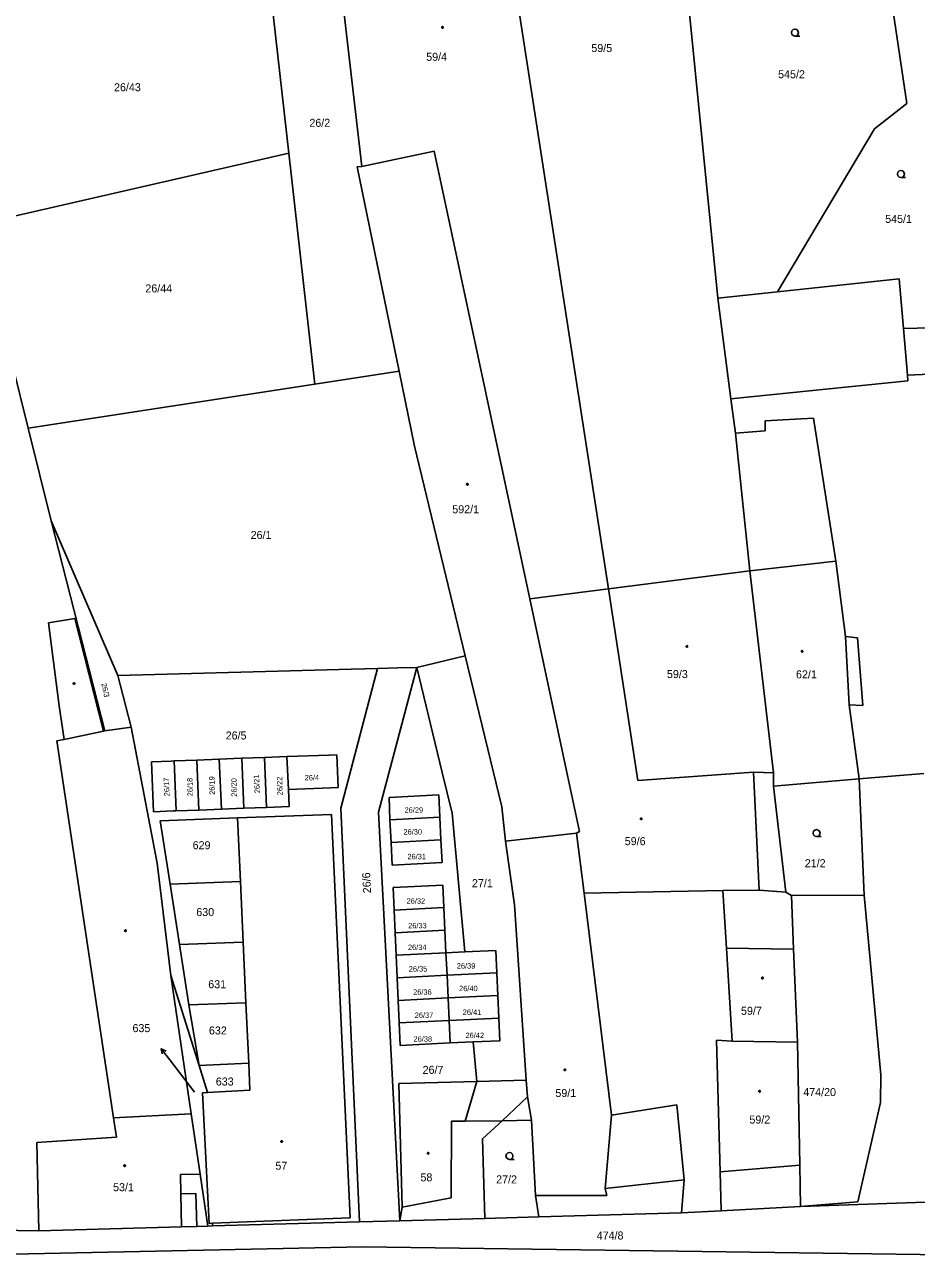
# Model space of a CAD drawing. Extents: x -757994 to -755874, y -1047691 to -1046119.
# Drawn here: x -757304.1 to -757209.4, y -1046980.7 to -1046849.4 of the extents above; entities that cross this region are included whole.
import ezdxf

# ---------------------------------------------------------------- set-up
doc = ezdxf.new("R2010")
doc.units = 0
doc.layers.add('katastrální mapa', color=7, linetype='Continuous')

msp = doc.modelspace()

# ---------------------------------------------------------------- linework, layer by layer
at = {"layer": 'katastrální mapa'}
for p, q in [((-757254.51, -1046829.16), (-757242.14, -1046909.26)), ((-757271.62, -1046835.82), (-757268.32, -1046864.4)), ((-757278.84, -1046838.68), (-757276.08, -1046863.01)), ((-757230.53, -1046878.4), (-757233.81, -1046845.4)), ((-757276.08, -1046863.01), (-757309.14, -1046870.58)), ((-757276.08, -1046863.01), (-757273.31, -1046887.52)), ((-757260.65, -1046862.78), (-757268.32, -1046864.4)), ((-757260.65, -1046862.78), (-757250.48, -1046910.32)), ((-757268.32, -1046864.4), (-757268.81, -1046864.45)), ((-757268.81, -1046864.45), (-757264.36, -1046886.13)), ((-757303.78, -1046892.18), (-757309.14, -1046870.58)), ((-757211.24, -1046876.35), (-757224.17, -1046877.72)), ((-757210.79, -1046881.6), (-757211.24, -1046876.35)), ((-757224.17, -1046877.72), (-757230.53, -1046878.4)), ((-757229.13, -1046889.09), (-757230.53, -1046878.4)), ((-757206.44, -1046881.51), (-757210.79, -1046881.6)), ((-757210.37, -1046886.58), (-757210.79, -1046881.6)), ((-757264.36, -1046886.13), (-757273.31, -1046887.52)), ((-757264.36, -1046886.13), (-757262.73, -1046894.1)), ((-757200.85, -1046886.14), (-757210.37, -1046886.58)), ((-757210.32, -1046887.18), (-757210.37, -1046886.58)), ((-757273.31, -1046887.52), (-757303.78, -1046892.18)), ((-757229.13, -1046889.09), (-757210.32, -1046887.18)), ((-757228.65, -1046892.73), (-757229.13, -1046889.09)), ((-757225.5, -1046891.42), (-757220.35, -1046891.15)), ((-757225.48, -1046892.47), (-757225.5, -1046891.42)), ((-757220.35, -1046891.15), (-757217.99, -1046906.33)), ((-757301.34, -1046902.02), (-757303.78, -1046892.18)), ((-757228.65, -1046892.73), (-757225.48, -1046892.47)), ((-757227.1, -1046907.35), (-757228.65, -1046892.73)), ((-757262.73, -1046894.1), (-757257.34, -1046916.35)), ((-757301.34, -1046902.02), (-757295.61, -1046924.32)), ((-757301.34, -1046902.02), (-757294.23, -1046918.44)), ((-757217.99, -1046906.33), (-757227.1, -1046907.35)), ((-757217.99, -1046906.33), (-757216.95, -1046914.33)), ((-757242.14, -1046909.26), (-757227.1, -1046907.35)), ((-757224.61, -1046928.8), (-757227.1, -1046907.35)), ((-757250.48, -1046910.32), (-757242.14, -1046909.26)), ((-757250.48, -1046910.32), (-757246.48, -1046929.06)), ((-757242.14, -1046909.26), (-757239, -1046929.62)), ((-757301.6, -1046912.85), (-757298.8, -1046912.42)), ((-757300.49, -1046921.68), (-757301.6, -1046912.85)), ((-757298.8, -1046912.42), (-757295.78, -1046924.36)), ((-757216.95, -1046914.33), (-757215.68, -1046914.44)), ((-757216.95, -1046914.33), (-757216.55, -1046921.56)), ((-757215.68, -1046914.44), (-757215.12, -1046921.64)), ((-757257.34, -1046916.35), (-757262.49, -1046917.6)), ((-757257.34, -1046916.35), (-757253.45, -1046932.4)), ((-757294.23, -1046918.44), (-757269.43, -1046917.78)), ((-757270.57, -1046932.54), (-757266.66, -1046917.71)), ((-757266.66, -1046917.71), (-757269.43, -1046917.78)), ((-757264.51, -1046917.65), (-757266.66, -1046917.71)), ((-757264.51, -1046917.65), (-757262.49, -1046917.6)), ((-757264.22, -1046924.15), (-757262.49, -1046917.6)), ((-757262.49, -1046917.6), (-757259.78, -1046928.74)), ((-757294.23, -1046918.44), (-757292.82, -1046923.93)), ((-757299.93, -1046925.24), (-757300.49, -1046921.68)), ((-757215.12, -1046921.64), (-757216.55, -1046921.56)), ((-757216.55, -1046921.56), (-757215.51, -1046929.42)), ((-757299.93, -1046925.24), (-757295.78, -1046924.36)), ((-757295.78, -1046924.36), (-757295.61, -1046924.32)), ((-757295.61, -1046924.32), (-757292.82, -1046923.93)), ((-757292.82, -1046923.93), (-757290.05, -1046938.37)), ((-757264.22, -1046924.15), (-757266.55, -1046932.97)), ((-757300.71, -1046925.41), (-757299.93, -1046925.24)), ((-757294.71, -1046965.41), (-757300.71, -1046925.41)), ((-757288.25, -1046927.53), (-757285.86, -1046927.44)), ((-757285.86, -1046927.44), (-757283.47, -1046927.35)), ((-757285.65, -1046932.74), (-757285.86, -1046927.44)), ((-757283.47, -1046927.35), (-757281.07, -1046927.25)), ((-757283.25, -1046932.64), (-757283.47, -1046927.35)), ((-757281.07, -1046927.25), (-757278.68, -1046927.16)), ((-757280.85, -1046932.55), (-757281.07, -1046927.25)), ((-757278.68, -1046927.16), (-757276.28, -1046927.07)), ((-757278.45, -1046932.46), (-757278.68, -1046927.16)), ((-757276.28, -1046927.07), (-757271.78, -1046926.9)), ((-757276.13, -1046930.57), (-757276.28, -1046927.07)), ((-757271.78, -1046926.9), (-757270.99, -1046926.87)), ((-757270.99, -1046926.87), (-757270.85, -1046930.36)), ((-757290.66, -1046927.62), (-757288.57, -1046927.54)), ((-757290.46, -1046932.92), (-757290.66, -1046927.62)), ((-757288.57, -1046927.54), (-757288.25, -1046927.53)), ((-757288.06, -1046932.83), (-757288.25, -1046927.53)), ((-757258.73, -1046933.06), (-757259.78, -1046928.74)), ((-757239, -1046929.62), (-757226.73, -1046928.72)), ((-757226.73, -1046928.72), (-757224.61, -1046928.8)), ((-757226.14, -1046941.25), (-757226.73, -1046928.72)), ((-757246.48, -1046929.06), (-757245.2, -1046935.03)), ((-757224.6, -1046930.2), (-757224.61, -1046928.8)), ((-757215.51, -1046929.42), (-757224.6, -1046930.2)), ((-757208.63, -1046928.85), (-757215.51, -1046929.42)), ((-757215.51, -1046929.42), (-757214.96, -1046941.79)), ((-757276.13, -1046930.57), (-757271.65, -1046930.39)), ((-757276.05, -1046932.37), (-757276.13, -1046930.57)), ((-757271.65, -1046930.39), (-757270.85, -1046930.36)), ((-757260.16, -1046931.13), (-757265.44, -1046931.4)), ((-757265.34, -1046933.79), (-757265.44, -1046931.4)), ((-757260.16, -1046931.13), (-757260.05, -1046933.51)), ((-757223.3, -1046941.45), (-757224.6, -1046930.2)), ((-757285.65, -1046932.74), (-757283.25, -1046932.64)), ((-757283.25, -1046932.64), (-757280.85, -1046932.55)), ((-757280.85, -1046932.55), (-757278.45, -1046932.46)), ((-757278.45, -1046932.46), (-757276.05, -1046932.37)), ((-757268.59, -1046976.47), (-757270.57, -1046932.54)), ((-757253.45, -1046932.4), (-757253.05, -1046936.05)), ((-757288.37, -1046932.84), (-757290.46, -1046932.92)), ((-757281.54, -1046933.58), (-757289.75, -1046933.89)), ((-757288.7, -1046940.6), (-757289.75, -1046933.89)), ((-757288.37, -1046932.84), (-757288.06, -1046932.83)), ((-757288.06, -1046932.83), (-757285.65, -1046932.74)), ((-757271.54, -1046933.2), (-757281.54, -1046933.58)), ((-757281.23, -1046940.32), (-757281.54, -1046933.58)), ((-757271.54, -1046933.2), (-757269.58, -1046976.04)), ((-757266.55, -1046932.97), (-757264.3, -1046976.35)), ((-757260.05, -1046933.51), (-757265.34, -1046933.79)), ((-757265.21, -1046936.18), (-757265.34, -1046933.79)), ((-757260.05, -1046933.51), (-757259.93, -1046935.91)), ((-757257.37, -1046947.8), (-757258.73, -1046933.06)), ((-757253.05, -1046936.05), (-757245.51, -1046935.21)), ((-757245.51, -1046935.21), (-757245.2, -1046935.03)), ((-757245.51, -1046935.21), (-757244.72, -1046941.56)), ((-757259.93, -1046935.91), (-757265.21, -1046936.18)), ((-757265.21, -1046936.18), (-757265.09, -1046938.58)), ((-757259.93, -1046935.91), (-757259.8, -1046938.3)), ((-757253.05, -1046936.05), (-757252.1, -1046942.8)), ((-757290.05, -1046938.37), (-757288.6, -1046950.31)), ((-757259.8, -1046938.3), (-757265.09, -1046938.58)), ((-757288.7, -1046940.6), (-757281.23, -1046940.32)), ((-757281.23, -1046940.32), (-757280.93, -1046946.76)), ((-757287.7, -1046947.02), (-757288.7, -1046940.6)), ((-757265, -1046940.97), (-757259.72, -1046940.7)), ((-757265, -1046940.97), (-757264.9, -1046943.37)), ((-757259.61, -1046943.1), (-757259.72, -1046940.7)), ((-757244.72, -1046941.56), (-757229.98, -1046941.28)), ((-757244.72, -1046941.56), (-757241.8, -1046965.13)), ((-757229.98, -1046941.28), (-757226.14, -1046941.25)), ((-757229.61, -1046947.39), (-757229.98, -1046941.28)), ((-757226.14, -1046941.25), (-757223.3, -1046941.45)), ((-757222.69, -1046941.8), (-757223.3, -1046941.45)), ((-757214.96, -1046941.79), (-757222.69, -1046941.8)), ((-757222.46, -1046947.53), (-757222.69, -1046941.8)), ((-757214.96, -1046941.79), (-757213.2, -1046960.86)), ((-757264.9, -1046943.37), (-757259.61, -1046943.1)), ((-757259.5, -1046945.49), (-757259.61, -1046943.1)), ((-757252.1, -1046942.8), (-757250.89, -1046961.43)), ((-757264.9, -1046943.37), (-757264.79, -1046945.77)), ((-757264.79, -1046945.77), (-757259.5, -1046945.49)), ((-757264.79, -1046945.77), (-757264.68, -1046948.16)), ((-757259.39, -1046947.89), (-757259.5, -1046945.49)), ((-757287.7, -1046947.02), (-757280.93, -1046946.76)), ((-757286.7, -1046953.44), (-757287.7, -1046947.02)), ((-757280.93, -1046946.76), (-757280.64, -1046953.2)), ((-757264.68, -1046948.16), (-757259.39, -1046947.89)), ((-757264.68, -1046948.16), (-757264.57, -1046950.56)), ((-757259.39, -1046947.89), (-757257.37, -1046947.8)), ((-757259.28, -1046950.28), (-757259.39, -1046947.89)), ((-757257.37, -1046947.8), (-757254.1, -1046947.65)), ((-757254.1, -1046947.65), (-757253.99, -1046950.04)), ((-757229, -1046957.27), (-757229.61, -1046947.39)), ((-757229.61, -1046947.39), (-757222.46, -1046947.53)), ((-757222.06, -1046957.37), (-757222.46, -1046947.53)), ((-757286.44, -1046964.99), (-757288.6, -1046950.31)), ((-757288.6, -1046950.31), (-757285.62, -1046959.85)), ((-757264.57, -1046950.56), (-757259.28, -1046950.28)), ((-757264.57, -1046950.56), (-757264.46, -1046952.95)), ((-757253.99, -1046950.04), (-757259.28, -1046950.28)), ((-757259.17, -1046952.68), (-757259.28, -1046950.28)), ((-757253.88, -1046952.44), (-757253.99, -1046950.04)), ((-757286.7, -1046953.44), (-757280.64, -1046953.2)), ((-757285.62, -1046959.85), (-757286.7, -1046953.44)), ((-757280.64, -1046953.2), (-757280.34, -1046959.63)), ((-757264.46, -1046952.95), (-757259.17, -1046952.68)), ((-757264.46, -1046952.95), (-757264.35, -1046955.35)), ((-757253.88, -1046952.44), (-757259.17, -1046952.68)), ((-757259.06, -1046955.08), (-757259.17, -1046952.68)), ((-757253.77, -1046954.84), (-757253.88, -1046952.44)), ((-757253.77, -1046954.84), (-757259.06, -1046955.08)), ((-757253.77, -1046954.84), (-757253.66, -1046957.23)), ((-757264.35, -1046955.35), (-757259.06, -1046955.08)), ((-757264.35, -1046955.35), (-757264.24, -1046957.75)), ((-757259.06, -1046955.08), (-757258.96, -1046957.47)), ((-757264.24, -1046957.75), (-757258.96, -1046957.47)), ((-757258.96, -1046957.47), (-757256.49, -1046957.36)), ((-757256.49, -1046957.36), (-757253.66, -1046957.23)), ((-757256.1, -1046961.56), (-757256.49, -1046957.36)), ((-757230.28, -1046971.14), (-757230.67, -1046957.18)), ((-757230.67, -1046957.18), (-757229, -1046957.27)), ((-757229, -1046957.27), (-757222.06, -1046957.37)), ((-757221.82, -1046970.44), (-757222.06, -1046957.37)), ((-757289.63, -1046958.09), (-757288.71, -1046959.28)), ((-757286.09, -1046962.68), (-757288.71, -1046959.28)), ((-757285.62, -1046959.85), (-757280.34, -1046959.63)), ((-757285.62, -1046959.85), (-757284.72, -1046962.73)), ((-757280.34, -1046959.63), (-757280.21, -1046962.49)), ((-757256.1, -1046961.56), (-757264.4, -1046961.78)), ((-757256.1, -1046961.56), (-757257.34, -1046965.79)), ((-757250.89, -1046961.43), (-757256.1, -1046961.56)), ((-757250.89, -1046961.43), (-757250.72, -1046963.2)), ((-757213.2, -1046960.86), (-757213.24, -1046963.78)), ((-757284.72, -1046962.73), (-757285.24, -1046962.76)), ((-757284.56, -1046976.63), (-757285.24, -1046962.76)), ((-757284.72, -1046962.73), (-757280.21, -1046962.49)), ((-757264.4, -1046961.78), (-757264.05, -1046974.89)), ((-757253.43, -1046965.73), (-757250.72, -1046963.2)), ((-757250.72, -1046963.2), (-757250.3, -1046965.68)), ((-757234.86, -1046964.04), (-757241.8, -1046965.13)), ((-757234.1, -1046972.01), (-757234.86, -1046964.04)), ((-757213.24, -1046963.78), (-757215.64, -1046974.34)), ((-757294.71, -1046965.41), (-757286.44, -1046964.99)), ((-757294.71, -1046965.41), (-757294.4, -1046967.49)), ((-757286.44, -1046964.99), (-757285.5, -1046971.39)), ((-757241.8, -1046965.13), (-757242.48, -1046972.91)), ((-757258.82, -1046965.79), (-757258.83, -1046973.92)), ((-757258.82, -1046965.79), (-757257.34, -1046965.79)), ((-757257.34, -1046965.79), (-757253.43, -1046965.73)), ((-757255.5, -1046967.66), (-757253.43, -1046965.73)), ((-757253.43, -1046965.73), (-757250.3, -1046965.68)), ((-757250.3, -1046965.68), (-757249.89, -1046973.65)), ((-757294.4, -1046967.49), (-757302.84, -1046968.03)), ((-757302.84, -1046968.03), (-757302.64, -1046977.41)), ((-757255.27, -1046976.1), (-757255.5, -1046967.66)), ((-757221.82, -1046970.44), (-757230.28, -1046971.14)), ((-757221.74, -1046974.83), (-757221.82, -1046970.44)), ((-757287.59, -1046971.44), (-757285.5, -1046971.39)), ((-757287.54, -1046973.49), (-757287.59, -1046971.44)), ((-757285.5, -1046971.39), (-757284.69, -1046976.91)), ((-757242.48, -1046972.91), (-757234.1, -1046972.01)), ((-757234.1, -1046972.01), (-757234.38, -1046975.52)), ((-757230.16, -1046975.29), (-757230.28, -1046971.14)), ((-757242.48, -1046972.91), (-757242.32, -1046973.68)), ((-757285.96, -1046973.45), (-757287.54, -1046973.49)), ((-757287.47, -1046976.99), (-757287.54, -1046973.49)), ((-757285.87, -1046976.95), (-757285.96, -1046973.45)), ((-757258.83, -1046973.92), (-757264.05, -1046974.89)), ((-757249.89, -1046973.65), (-757249.51, -1046975.94)), ((-757242.32, -1046973.68), (-757249.89, -1046973.65)), ((-757221.74, -1046974.83), (-757203.42, -1046974.2)), ((-757215.64, -1046974.34), (-757221.74, -1046974.83)), ((-757269.58, -1046976.04), (-757284.2, -1046976.62)), ((-757264.05, -1046974.89), (-757264.3, -1046976.35)), ((-757249.51, -1046975.94), (-757255.27, -1046976.1)), ((-757234.38, -1046975.52), (-757249.51, -1046975.94)), ((-757230.16, -1046975.29), (-757234.38, -1046975.52)), ((-757221.74, -1046974.83), (-757230.16, -1046975.29)), ((-757302.64, -1046977.41), (-757307.44, -1046977.34)), ((-757287.47, -1046976.99), (-757302.64, -1046977.41)), ((-757285.87, -1046976.95), (-757287.47, -1046976.99)), ((-757284.69, -1046976.91), (-757285.87, -1046976.95)), ((-757284.2, -1046976.9), (-757284.69, -1046976.91)), ((-757284.2, -1046976.62), (-757284.56, -1046976.63)), ((-757268.59, -1046976.47), (-757284.2, -1046976.9)), ((-757284.2, -1046976.62), (-757284.2, -1046976.9)), ((-757264.3, -1046976.35), (-757268.59, -1046976.47)), ((-757255.27, -1046976.1), (-757264.3, -1046976.35)), ((-757268.25, -1046979.12), (-757354.94, -1046980.95)), ((-757203.07, -1046980.03), (-757268.25, -1046979.12))]:
    msp.add_line(p, q, dxfattribs=at)
for points in [[(-757212.67, -1046842.68), (-757210.45, -1046857.71), (-757213.88, -1046860.42), (-757224.17, -1046877.72)], [(-757222.31, -1046850.57), (-757222.5, -1046850.52), (-757222.64, -1046850.39), (-757222.69, -1046850.2), (-757222.64, -1046850.01), (-757222.5, -1046849.88), (-757222.32, -1046849.83), (-757222.13, -1046849.88), (-757222, -1046850.01), (-757221.95, -1046850.21), (-757222, -1046850.4), (-757222.13, -1046850.53), (-757222.32, -1046850.58), (-757221.82, -1046850.58)], [(-757211.06, -1046865.58), (-757211.25, -1046865.53), (-757211.39, -1046865.4), (-757211.44, -1046865.21), (-757211.39, -1046865.02), (-757211.25, -1046864.89), (-757211.07, -1046864.84), (-757210.88, -1046864.89), (-757210.75, -1046865.02), (-757210.7, -1046865.22), (-757210.75, -1046865.41), (-757210.88, -1046865.54), (-757211.07, -1046865.59), (-757210.57, -1046865.59)], [(-757220.02, -1046935.55), (-757220.21, -1046935.5), (-757220.35, -1046935.37), (-757220.4, -1046935.18), (-757220.35, -1046935), (-757220.21, -1046934.86), (-757220.03, -1046934.81), (-757219.84, -1046934.86), (-757219.71, -1046935), (-757219.66, -1046935.19), (-757219.71, -1046935.38), (-757219.84, -1046935.51), (-757220.03, -1046935.56), (-757219.53, -1046935.56)], [(-757289.52, -1046958.64), (-757289.63, -1046958.09), (-757289.12, -1046958.34)], [(-757252.64, -1046969.84), (-757252.83, -1046969.79), (-757252.97, -1046969.66), (-757253.02, -1046969.47), (-757252.97, -1046969.28), (-757252.83, -1046969.15), (-757252.65, -1046969.1), (-757252.46, -1046969.15), (-757252.33, -1046969.28), (-757252.28, -1046969.48), (-757252.33, -1046969.67), (-757252.46, -1046969.8), (-757252.65, -1046969.85), (-757252.15, -1046969.85)]]:
    msp.add_lwpolyline(points, dxfattribs=at)
for points in [[(-757259.75, -1046849.55), (-757259.7, -1046849.57), (-757259.68, -1046849.61), (-757259.67, -1046849.64), (-757259.68, -1046849.69), (-757259.72, -1046849.72), (-757259.75, -1046849.73), (-757259.79, -1046849.71), (-757259.83, -1046849.68), (-757259.84, -1046849.64), (-757259.83, -1046849.6), (-757259.78, -1046849.56)], [(-757257.13, -1046898.07), (-757257.08, -1046898.08), (-757257.05, -1046898.12), (-757257.04, -1046898.15), (-757257.05, -1046898.2), (-757257.1, -1046898.23), (-757257.13, -1046898.24), (-757257.18, -1046898.22), (-757257.21, -1046898.19), (-757257.22, -1046898.15), (-757257.21, -1046898.11), (-757257.17, -1046898.07)], [(-757233.8, -1046915.28), (-757233.75, -1046915.29), (-757233.73, -1046915.34), (-757233.72, -1046915.37), (-757233.73, -1046915.42), (-757233.77, -1046915.45), (-757233.8, -1046915.46), (-757233.85, -1046915.44), (-757233.88, -1046915.41), (-757233.89, -1046915.37), (-757233.88, -1046915.33), (-757233.84, -1046915.29)], [(-757221.56, -1046915.8), (-757221.51, -1046915.82), (-757221.49, -1046915.86), (-757221.48, -1046915.89), (-757221.49, -1046915.94), (-757221.53, -1046915.97), (-757221.56, -1046915.98), (-757221.6, -1046915.96), (-757221.64, -1046915.93), (-757221.65, -1046915.89), (-757221.64, -1046915.85), (-757221.6, -1046915.81)], [(-757298.85, -1046919.24), (-757298.81, -1046919.31), (-757298.85, -1046919.39), (-757298.95, -1046919.39), (-757298.99, -1046919.31), (-757298.95, -1046919.24)], [(-757238.65, -1046933.59), (-757238.6, -1046933.6), (-757238.58, -1046933.64), (-757238.57, -1046933.67), (-757238.58, -1046933.72), (-757238.61, -1046933.75), (-757238.65, -1046933.76), (-757238.7, -1046933.74), (-757238.73, -1046933.71), (-757238.74, -1046933.67), (-757238.73, -1046933.62), (-757238.69, -1046933.59)], [(-757293.4, -1046945.47), (-757293.35, -1046945.54), (-757293.4, -1046945.62), (-757293.48, -1046945.62), (-757293.53, -1046945.54), (-757293.48, -1046945.47)], [(-757225.78, -1046950.48), (-757225.73, -1046950.49), (-757225.71, -1046950.54), (-757225.7, -1046950.57), (-757225.71, -1046950.62), (-757225.75, -1046950.65), (-757225.78, -1046950.66), (-757225.83, -1046950.64), (-757225.85, -1046950.61), (-757225.86, -1046950.57), (-757225.85, -1046950.52), (-757225.82, -1046950.49)], [(-757246.76, -1046960.24), (-757246.71, -1046960.25), (-757246.69, -1046960.3), (-757246.68, -1046960.33), (-757246.69, -1046960.38), (-757246.73, -1046960.41), (-757246.76, -1046960.42), (-757246.8, -1046960.4), (-757246.84, -1046960.37), (-757246.85, -1046960.33), (-757246.84, -1046960.28), (-757246.79, -1046960.25)], [(-757226.08, -1046962.51), (-757226.03, -1046962.52), (-757226, -1046962.57), (-757225.99, -1046962.6), (-757226, -1046962.65), (-757226.04, -1046962.68), (-757226.08, -1046962.69), (-757226.12, -1046962.67), (-757226.16, -1046962.64), (-757226.17, -1046962.6), (-757226.16, -1046962.55), (-757226.11, -1046962.52)], [(-757276.84, -1046967.85), (-757276.79, -1046967.86), (-757276.76, -1046967.9), (-757276.75, -1046967.93), (-757276.76, -1046967.98), (-757276.8, -1046968.01), (-757276.84, -1046968.02), (-757276.89, -1046968), (-757276.92, -1046967.97), (-757276.93, -1046967.93), (-757276.92, -1046967.89), (-757276.88, -1046967.85)], [(-757261.27, -1046969.11), (-757261.22, -1046969.12), (-757261.2, -1046969.16), (-757261.19, -1046969.19), (-757261.2, -1046969.23), (-757261.24, -1046969.27), (-757261.27, -1046969.27), (-757261.32, -1046969.26), (-757261.35, -1046969.23), (-757261.35, -1046969.19), (-757261.35, -1046969.15), (-757261.3, -1046969.11)], [(-757293.51, -1046970.42), (-757293.46, -1046970.43), (-757293.44, -1046970.47), (-757293.43, -1046970.5), (-757293.44, -1046970.54), (-757293.48, -1046970.58), (-757293.51, -1046970.59), (-757293.55, -1046970.57), (-757293.59, -1046970.54), (-757293.6, -1046970.5), (-757293.59, -1046970.46), (-757293.54, -1046970.42)]]:
    msp.add_lwpolyline(points, close=True, dxfattribs=at)

# ---------------------------------------------------------------- texts
for s, height, p in [('59/4', 0.85, (-757261.49, -1046853.19)), ('59/5', 0.85, (-757243.95, -1046852.26)), ('545/2', 0.85, (-757224.11, -1046855.04)), ('26/43', 0.85, (-757294.65, -1046856.42)), ('26/2', 0.85, (-757273.9, -1046860.2)), ('545/1', 0.85, (-757212.74, -1046870.4)), ('26/44', 0.85, (-757291.32, -1046877.78)), ('592/1', 0.85, (-757258.72, -1046901.23)), ('26/1', 0.85, (-757280.14, -1046903.96)), ('59/3', 0.85, (-757235.92, -1046918.73)), ('62/1', 0.85, (-757222.21, -1046918.76)), ('26/5', 0.85, (-757282.79, -1046925.25)), ('26/4', 0.57, (-757274.4, -1046929.59)), ('26/29', 0.57, (-757263.79, -1046933.02)), ('26/30', 0.57, (-757263.9, -1046935.34)), ('629', 0.85, (-757286.3, -1046936.9)), ('59/6', 0.85, (-757240.4, -1046936.47)), ('26/31', 0.57, (-757263.48, -1046937.96)), ('21/2', 0.85, (-757221.28, -1046938.81)), ('27/1', 0.85, (-757256.63, -1046940.93)), ('630', 0.85, (-757285.91, -1046944)), ('26/32', 0.57, (-757263.57, -1046942.68)), ('26/33', 0.57, (-757263.41, -1046945.3)), ('26/34', 0.57, (-757263.43, -1046947.6)), ('26/35', 0.57, (-757263.34, -1046949.89)), ('26/39', 0.57, (-757258.24, -1046949.57)), ('631', 0.85, (-757284.64, -1046951.66)), ('26/36', 0.57, (-757262.88, -1046952.35)), ('26/40', 0.57, (-757258, -1046951.97)), ('59/7', 0.85, (-757228.05, -1046954.48)), ('26/37', 0.57, (-757262.71, -1046954.81)), ('26/41', 0.57, (-757257.61, -1046954.49)), ('635', 0.85, (-757292.69, -1046956.32)), ('632', 0.85, (-757284.57, -1046956.57)), ('26/42', 0.57, (-757257.31, -1046956.95)), ('26/38', 0.57, (-757262.84, -1046957.33)), ('26/7', 0.85, (-757261.87, -1046960.75)), ('633', 0.85, (-757283.84, -1046961.99)), ('635', 0.05, (-757286.15, -1046962.68)), ('59/1', 0.85, (-757247.77, -1046963.21)), ('474/20', 0.85, (-757221.44, -1046963.11)), ('59/2', 0.85, (-757227.16, -1046966.03)), ('57', 0.85, (-757277.51, -1046970.93)), ('58', 0.85, (-757262.1, -1046972.16)), ('27/2', 0.85, (-757254.06, -1046972.38)), ('53/1', 0.85, (-757294.75, -1046973.21)), ('474/8', 0.85, (-757243.38, -1046978.34))]:
    msp.add_text(s, height=height, dxfattribs=at).set_placement(p)
for s, height, rotation, p in [('26/3', 0.57, 282.0098, (-757296, -1046919.32)), ('26/17', 0.57, 92.017, (-757288.75, -1046931.26)), ('26/18', 0.57, 91.2722, (-757286.28, -1046931.28)), ('26/19', 0.57, 91.616, (-757283.93, -1046931.12)), ('26/20', 0.57, 91.1003, (-757281.6, -1046931.32)), ('26/21', 0.57, 92.8765, (-757279.15, -1046930.94)), ('26/22', 0.57, 90.6992, (-757276.75, -1046931.17)), ('26/6', 0.85, 92.5327, (-757267.35, -1046941.56))]:
    msp.add_text(s, height=height, rotation=rotation, dxfattribs=at).set_placement(p)

doc.saveas('drawing.dxf')
